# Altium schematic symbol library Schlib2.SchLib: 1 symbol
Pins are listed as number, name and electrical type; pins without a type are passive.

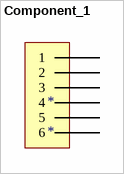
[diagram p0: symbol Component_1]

## Component_1
designator *
pins: 5 1, 6 2, 7 3, 8 4, 9 5, 10 6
